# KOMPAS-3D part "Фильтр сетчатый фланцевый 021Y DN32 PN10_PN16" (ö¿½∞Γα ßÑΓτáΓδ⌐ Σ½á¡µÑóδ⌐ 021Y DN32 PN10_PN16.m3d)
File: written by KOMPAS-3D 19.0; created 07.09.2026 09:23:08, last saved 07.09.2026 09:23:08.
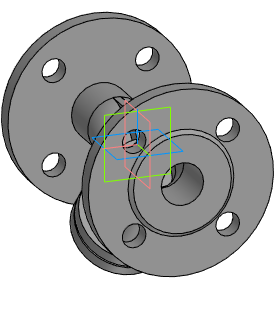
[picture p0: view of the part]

Document properties: Автор: Энергия; Полное имя файла: Z:\3.Личные\sachek\Dendor\_3D для проектировщиков\8.3 Фильтр сетчатый 021Y\021Y_STP\Фильтр сетчатый фланцевый 021Y DN32 PN10_PN16.m3d

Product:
- Part/product: Фильтр сетчатый фланцевый 021Y DN32 PN10_PN16

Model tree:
1. Операция без истории:1  (labels: Фильтр сетчатый фланцевый 021Y DN32 PN10_PN16)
